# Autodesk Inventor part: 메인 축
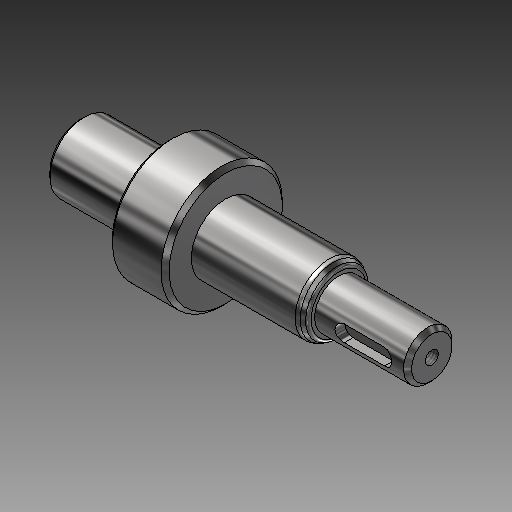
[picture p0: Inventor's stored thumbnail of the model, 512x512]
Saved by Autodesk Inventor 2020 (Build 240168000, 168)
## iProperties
Created: 2016-04
Part Number: 메인 축
Document SubType Name: Modeling
Designer: mdu
Density: 7.86 g/cm^3
Mass: 230.24 g
Surface Area: 74.3518 cm^2
Volume: 29.2926 cm^3
Material: 강철, 연강
Appearance: 반광택
Author: mdu
Revision Number: 1
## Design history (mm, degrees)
sketch "스케치1"
  geometry: L1 (10.497, -57.5)-(97.497, -57.5); L2 (10.497, -66)-(32.497, -66); L3 (32.497, -72.5)-(46.5, -72.5); L4 (46.5, -66)-(74.497, -66); L5 (97.497, -63.5)-(97.497, -57.5); L6 (10.497, -66)-(10.497, -57.5); L7 (46.5, -69.749)-(46.5, -45.251) reference; L8 (46.5, -72.5)-(46.5, -66); L9 (32.497, -72.5)-(32.497, -66); L10 (32.497, -35)-(32.497, -80) reference; L11 (97.497, -63.5)-(74.497, -63.5); L12 (74.497, -63.5)-(74.497, -66); 3 further points
  constraints: 20 end point, 4 perpendicular, 3 point on line, 2 parallel, 1 collinear, 1 horizontal, 1 midpoint
  dimensions: "d0" = 17 diameter of L4 L1; "d1" = 30 diameter of L3 L1; "d2" = 22 distance of L2.start L2.end; "d5" = 17 diameter of L2 L1; "d19" = 65 distance between parallel lines of L5 L9; "d21" = 50.99692 distance between parallel lines of L5 L8 (derived); "d22" = 23 distance between parallel lines of L5 L12; "d23" = 12 diameter of L11 L1
revolve "회전1" sketch "스케치1" stored, may be unused: angle "d4" = 90 deg
chamfer "모따기1" distance "d6" = 1; stored, may be unused: second distance "d7" = 2, angle "d8" = 45 deg
node "작업 평면1"
sketch "스케치2"
  geometry: L1 (10.497, -65)-(10.497, -50) reference; L2 (16.997, -55)-(25.997, -55); L3 (25.997, -60)-(16.997, -60); A1 r 2.5 centre (25.997, -57.5) between (25.997, -60) and (25.997, -55); A2 r 2.5 centre (16.997, -57.5) between (16.997, -55) and (16.997, -60); 2 further points
  constraints: 4 end point, 4 point on circle, 4 tangent, 2 centre point, 1 horizontal alignment, 1 midpoint, 1 parallel, 1 perpendicular
  dimensions: "d9" = 5 distance between parallel lines of L3 L2; "d10" = 14 dimension on A1 A2; "d11" = 4 distance edge to line of A2 L1
extrude "돌출1" cut sketch "스케치2" distance "d12" = 3; taper "d13" = 0 deg
node "작업 평면2"
sketch "스케치3"
  geometry: L1 (91.497, -55.5)-(81.497, -55.5); L2 (81.497, -59.5)-(91.497, -59.5); L3 (97.497, -52.5)-(97.497, -62.5) reference; A1 r 2 centre (81.497, -57.5) between (81.497, -55.5) and (81.497, -59.5); A2 r 2 centre (91.497, -57.5) between (91.497, -59.5) and (91.497, -55.5); 4 further points
  constraints: 4 end point, 4 point on circle, 4 tangent, 2 centre point, 2 horizontal, 2 point on line, 1 horizontal alignment, 1 midpoint, 1 vertical alignment
  dimensions: "d32" = 14 dimension on A2 A1; "d34" = 4 distance edge to line of A2 L3; "d35" = 4 distance between parallel lines of L2 L1
extrude "돌출2" cut sketch "스케치3" distance "d16" = 2.5; taper "d17" = 0 deg
sketch "스케치4"
  geometry: L1 (74.497, -50.05)-(72.678, -49); L2 (74.497, -49)-(46.5, -49) reference; L3 (74.497, -49)-(74.497, -66) reference; L4 (74.497, -66)-(46.5, -66) reference; L5 (74.497, -57.5)-(60.711, -57.5); 1 further point
  constraints: 4 end point, 2 point on line, 1 midpoint, 1 parallel
  dimensions: "d24" = 14.9 diameter of L1.start L5; "d26" = 30 deg angle of L2 L1
revolve "회전2" sketch "스케치4" stored, may be unused: angle "d28" = 90 deg
fillet "모깎기1" dims "d29" = 1
fillet "모깎기2" dims "d30" = 2
hole "구멍1" diameter "d38" = 3.242; stored, may be unused: countersink angle "d42" = 90 deg, drill point angle "d44" = 118 deg; dims "d39" = 8, "d40" = 4, "d41" = 2, "d43" = 10, "d45" = 10, "d46" = 10
node "솔리드1"
node "참조4"
node "참조5"
other parameters: "d20" = 6, "d47" = -8.5
